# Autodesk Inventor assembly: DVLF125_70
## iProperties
Created: 2010-04
Part Number: DVLF125_70
Document SubType Name: Assembly
Designer: TB
Mass: 5321.53 g
Surface Area: 5266.97 cm^2
Volume: 5321.53 cm^3
Density: 1 g/cm^3
Description: KM DVLF 125/70 - 100 mm
Slaglengde: 100.000 mm
Author: TB
